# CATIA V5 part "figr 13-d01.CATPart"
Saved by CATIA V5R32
Part number: Part1
Bounding box of the stored display mesh (mm): x -175 to 175, y -250 to 250, z -108 to 0
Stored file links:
  D:\PROJECTS\Project 2022\CATIA V5 6R 2022\Resources\Part Files\c13_catia_v5_6r2022_prt\c13_catia_v5-6r2022_figr_13-8\figr 13-d01.CATPart
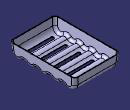
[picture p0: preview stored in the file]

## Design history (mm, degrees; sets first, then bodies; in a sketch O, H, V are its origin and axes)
Set1
  Plane1: type Offset, RefPlane yz-plane, Offset 120
  Plane2: type Offset, RefPlane xy-plane, Offset 108, reversed
Body1 (main body)
  Sketch1 on yz-plane, origin (0, 0, 0), H (0, 1, 0), V (0, 0, 1)
    line L1 (-250, 0) -> (250, 0)
    point P1 (-250, 0)
    point P2 (250, 0)
    line L2 (-250, 0) -> (-250, -100)
    point P3 (-250, -50)
    construction arc A1 centre (-200, -50) radius 50 from (-250, -50) to (-161.5385, -81.9486) ccw
    point P4 (-200, -50)
    construction arc A2 centre (-150, -91.5331) radius 15 from (-161.5385, -81.9486) to (-138.4615, -81.9486) cw
    construction arc A3 centre (-100, -50) radius 50 from (-138.4615, -81.9486) to (-61.5385, -81.9486) ccw
    point P8 (-100, -50)
    construction arc A4 centre (-50, -91.5331) radius 15 from (-61.5385, -81.9486) to (-38.4615, -81.9486) cw
    point P10 (-50, -91.5331)
    construction arc A5 centre (0, -50) radius 50 from (-38.4615, -81.9486) to (38.4615, -81.9486) ccw
    point P12 (0, -50)
    construction arc A6 centre (50, -91.5331) radius 15 from (38.4615, -81.9486) to (61.5385, -81.9486) cw
    point P14 (50, -91.5331)
    construction arc A7 centre (100, -50) radius 50 from (61.5385, -81.9486) to (138.4615, -81.9486) ccw
    point P16 (100, -50)
    construction arc A8 centre (150, -91.5331) radius 15 from (138.4615, -81.9486) to (161.5385, -81.9486) cw
    construction arc A9 centre (200, -50) radius 50 from (161.5385, -81.9486) to (250, -50) ccw
    point P21 (250, -50)
    line L3 (250, -100) -> (250, 0)
    construction line L4 (200, -50) -> (-159.8058, -50)
    construction line L5 (-150, -91.5331) -> (150, -91.5331)
    line L6 (-250, -100) -> (250, -100)
    length L1 = 500
    radius A1 = 50
    radius A3 = 50
    radius A5 = 50
    radius A7 = 50
    radius A9 = 50
    distance P2 V = 250
    radius A2 = 15
    radius A4 = 15
    radius A6 = 15
    radius A8 = 15
    coincidence: P1 H, L4 P4, P16 L4, P12 L4, P8 L4, P10 L5, P14 L5, P3 L2, P21 L3
    horizontal: L1 H, L4 H, L5 H, L6 H
    vertical: L2 V, L3 V
    tangency: A1 L1, A1 L2, A2 A1, A3 A2, A4 A3, A5 A4, A6 A5, A7 A6, A8 A7, A9 A8, L3 A9, L6 A1
  Pad1: profile Sketch1, direction (1, 0, 0), length 175, mirrored extent
  Draft1: Angle -5, Neutral face of Pad1, PullDir face of Pad1, SupportToDraft (face of Pad1; face of Pad1; face of Pad1; face of Pad1)
  Sketch2 on yz-plane, origin (0, 0, 0), H (0, 1, 0), V (0, 0, 1)
    point P1 (-245.2443, -54.3578)
    arc A1 centre (-195.4346, -50) radius 50 from (-245.2443, -54.3578) to (-162.8621, -87.9346) ccw
    arc A2 centre (-146.5759, -106.902) radius 25 from (-162.8621, -87.9346) to (-130.2897, -87.9346) cw
    arc A3 centre (-97.7173, -50) radius 50 from (-130.2897, -87.9346) to (-65.1449, -87.9346) ccw
    point P6 (-97.7173, -50)
    arc A4 centre (-48.8586, -106.902) radius 25 from (-65.1449, -87.9346) to (-32.5724, -87.9346) cw
    point P8 (-48.8586, -106.902)
    arc A5 centre (0, -50) radius 50 from (-32.5724, -87.9346) to (32.5724, -87.9346) ccw
    point P10 (0, -50)
    arc A6 centre (48.8586, -106.902) radius 25 from (32.5724, -87.9346) to (65.1449, -87.9346) cw
    point P12 (48.8586, -106.902)
    arc A7 centre (97.7173, -50) radius 50 from (65.1449, -87.9346) to (130.2897, -87.9346) ccw
    point P14 (97.7173, -50)
    arc A8 centre (146.5759, -106.902) radius 25 from (130.2897, -87.9346) to (162.8621, -87.9346) cw
    arc A9 centre (195.4346, -50) radius 50 from (162.8621, -87.9346) to (245.2443, -54.3578) ccw
    point P19 (245.2443, -54.3578)
    reference projected line E1 (241.2511, -100) -> (250, 0) from edge [face of Pad1 | face of Pad1]
    reference projected line E2 (241.2511, -100) -> (250, 0) from edge [face of Pad1 | face of Pad1]
    reference projected line E3 (-250, 0) -> (-241.2511, -100) from edge [face of Pad1 | face of Pad1]
    reference projected line E4 (-250, 0) -> (-241.2511, -100) from edge [face of Pad1 | face of Pad1]
    reference projected line E5 (241.2511, -100) -> (-241.2511, -100) from edge [face of Pad1 | face of Pad1]
    reference projected line E6 (241.2511, -100) -> (-241.2511, -100) from edge [face of Pad1 | face of Pad1]
    reference projected line E7 (241.2511, -100) -> (-241.2511, -100) from edge [face of Pad1 | face of Pad1]
    reference projected line E8 (241.2511, -100) -> (-241.2511, -100) from edge [face of Pad1 | face of Pad1]
    reference projected line E9 (241.2511, -100) -> (-241.2511, -100) from edge [face of Pad1 | face of Pad1]
    construction line L1 (-195.4346, -50) -> (195.4346, -50)
    axis line L2 (146.5759, -106.902) -> (-146.5759, -106.902)
    radius A1 = 50
    radius A2 = 25
    radius A4 = 25
    radius A6 = 25
    radius A8 = 25
    tangency: A2 A1, A3 A2, A4 A3, A5 A4, A6 A5, A7 A6, A8 A7, A9 A8, A9 E1, A1 E4, A1 E5, A3 E6, A5 E7, A7 E8, A9 E9
    coincidence: P19 E2, P1 E3, P6 L1, P10 L1, P14 L1, P8 L2, L2 P12
    horizontal: L1 H, L2 H
  Pocket1: profile Sketch2, direction (-1, 0, 0), length 175, opposite side through (limit type 3)
  Fillet1: radius 25, on 2 edges
  Shell1: ExtOffset 0, Face face of Pad1, IntOffset 5
  Sketch3 on xy-plane, origin (0, 0, 0), H (1, 0, 0), V (0, 1, 0)
    construction line L1 (-105, -200) -> (105, -200)
    point P2 (105, -200)
    line L2 (-105, -188) -> (105, -188)
    line L3 (105, -212) -> (-105, -212)
    arc A1 centre (105, -200) radius 12 from (105, -188) to (105, -212) cw
    arc A2 centre (-105, -200) radius 12 from (-105, -212) to (-105, -188) cw
    reference projected line E1 (-175, -250) -> (175, -250) from edge [face of Pad1 | face of Pad1]
    reference projected line E2 (175, -250) -> (175, 250) from edge [face of Pad1 | face of Pad1]
    distance L1 E1 = 50
    distance E2 P2 = 70
    radius A1 = 12
    length L1 = 210
    horizontal: L1 H
    tangency: A1 L2, A2 L2, A1 L3, A2 L3
    parallelism: L1 L2
  Pocket2: profile Sketch3, direction (0, 0, -1), through (limit type 3)
  RectPattern1: of Pocket2, direction 1 instances 5, spacing 101, along edge [face of Pad1 | face of Pad1]
  Sketch4 on Plane2, origin (0, 0, -108), H (1, 0, 0), V (0, 1, 0)
    circle A1 centre (130, -200) radius 5
    point P1 (130, -200)
    reference projected line E1 (175, -250) -> (175, 250) from edge [face of Pad1 | face of Pad1]
    reference projected line E2 (-175, -250) -> (175, -250) from edge [face of Pad1 | face of Pad1]
    distance P1 E1 = 45
    distance P1 E2 = 50
    radius A1 = 5
  Pad2: profile Sketch4, direction (0, 0, 1), up to the existing solid (limit type 2)
  Draft2: Angle -5, Neutral face of Pad2, PullDir face of Pad1, SupportToDraft face of Pad2
  Fillet2: radius 2, on edge [face of Pad2 | face of Pad2]
  RectPattern2: of Pad2, Sketch4, Draft2, Fillet2, direction 1 instances 2, spacing 402, along edge [face of Pad1 | face of Pad1], direction 2 instances 2, spacing 260, along edge [face of Pad1 | face of Pad1] reversed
